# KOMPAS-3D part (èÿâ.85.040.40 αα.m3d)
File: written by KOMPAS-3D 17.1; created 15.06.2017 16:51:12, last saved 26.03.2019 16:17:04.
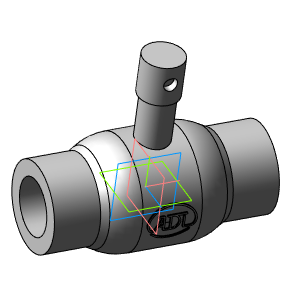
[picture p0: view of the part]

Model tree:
1. Операция без истории:3  (labels: Сталь 20  ГОСТ 1050-88)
